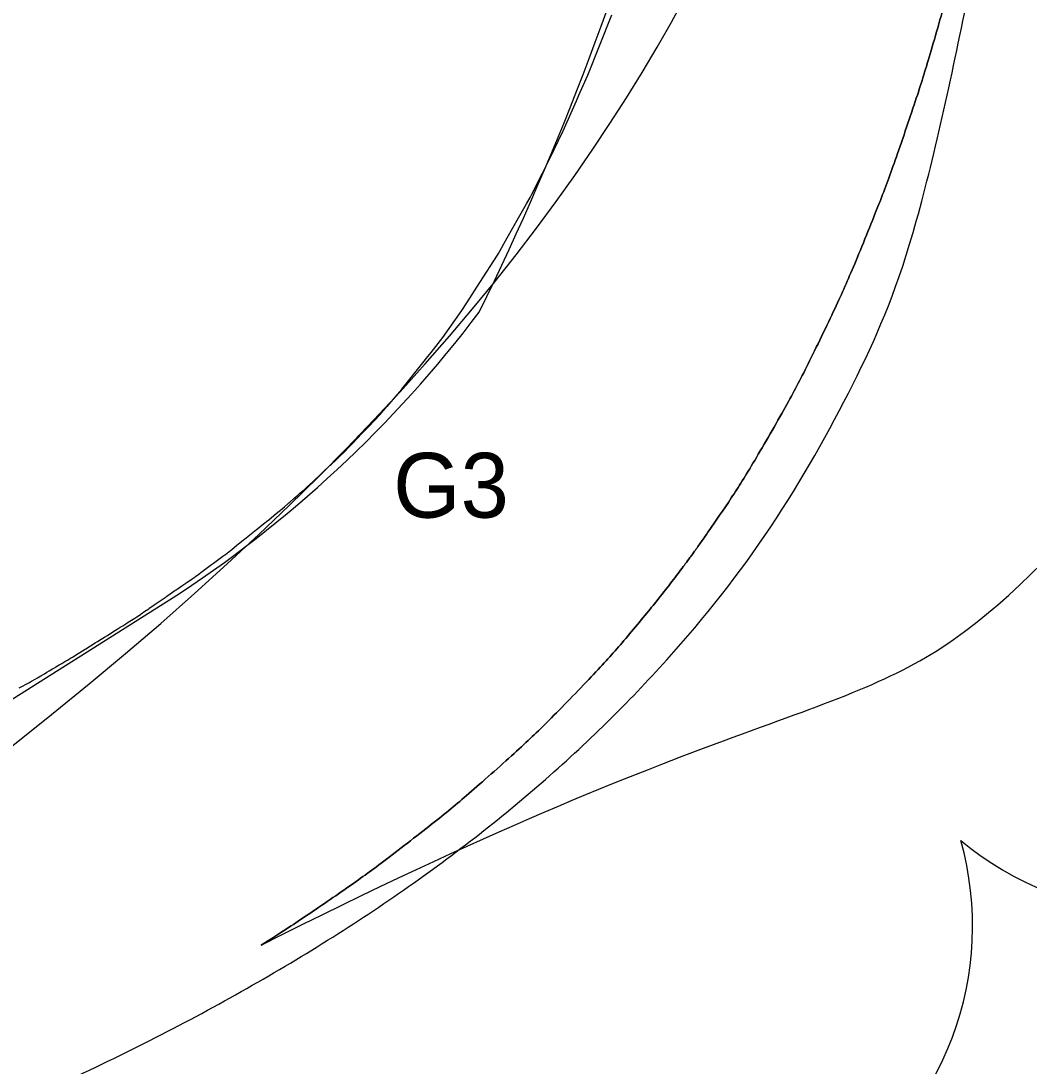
# Model space of a CAD drawing. Extents: x 0 to 512122, y 0 to 6212554.
# Drawn here: x 511655.18 to 511674.62, y 6211397.6 to 6211417.76 of the extents above; entities that cross this region are included whole.
import ezdxf

# ---------------------------------------------------------------- set-up
doc = ezdxf.new("R2010")
doc.units = 0
for name, color, linetype in [('_G3S_Slået græsser', 7, 'Continuous'), ('_Paths', 7, 'Continuous'), ('_S1_rabarber', 7, 'Continuous'), ('Clouds', 7, 'Continuous'), ('TV_U_AFM_Symbl_Gul', 7, 'Continuous'), ('TV_U_LYS_Nyx330-Trafiksti-x2', 7, 'Continuous')]:
    doc.layers.add(name, color=color, linetype=linetype)

msp = doc.modelspace()

# ---------------------------------------------------------------- linework, layer by layer
at = {"layer": '_G3S_Slået græsser'}
msp.add_lwpolyline([(511640.462, 6211394.164), (511651.9, 6211402.721), (511658.046, 6211406.592)], dxfattribs=at)
for centre, radius, start, end in [((511613.419, 6211436.972), 56.363, 333.8642, 344.7053), ((511645.363, 6211426.225), 23.373, 302.8622, 322.9556)]:
    msp.add_arc(centre, radius, start, end, dxfattribs=at)
at = {"layer": '_Paths'}
for points, degree in [([(511640.462, 6211394.164), (511666.005, 6211408.809), (511672.517, 6211429.483), (511676.559, 6211451.282), (511690.481, 6211465.664), (511705.077, 6211478.474), (511709.825, 6211494.014), (511640.462, 6211394.164), (511709.825, 6211494.014)], 3), ([(511651.32, 6211395.399), (511670.02, 6211402.099), (511675.836, 6211429.41), (511675.931, 6211450.773), (511691.497, 6211463.947), (511708.899, 6211474.665), (511711.288, 6211488), (511712.286, 6211493.573)], 2)]:
    msp.add_open_spline(points, degree=degree, dxfattribs=at)
at = {"layer": '_S1_rabarber'}
for points in [[(511659.815, 6211399.937), (511668.561, 6211404.361), (511673.198, 6211404.114), (511679.922, 6211414.023), (511688.007, 6211417.394), (511690.187, 6211425.291), (511687.866, 6211432.031), (511684.336, 6211437.489), (511684.603, 6211441.593), (511684.719, 6211443.38)], [(511659.815, 6211399.937), (511668.561, 6211404.361), (511673.198, 6211404.114), (511679.922, 6211414.023), (511688.007, 6211417.394), (511690.187, 6211425.291), (511687.866, 6211432.031), (511684.336, 6211437.489), (511684.603, 6211441.593), (511684.719, 6211443.38)], [(511659.815, 6211399.937), (511660.213, 6211400.189), (511660.606, 6211400.447), (511661.573, 6211401.109), (511662.14, 6211401.52), (511663.246, 6211402.378), (511663.784, 6211402.823), (511664.828, 6211403.751), (511665.333, 6211404.234), (511666.306, 6211405.238), (511666.774, 6211405.761), (511667.445, 6211406.576), (511667.663, 6211406.853), (511667.929, 6211407.206), (511667.982, 6211407.277), (511668.087, 6211407.42), (511668.139, 6211407.491), (511668.294, 6211407.707), (511668.396, 6211407.852), (511668.897, 6211408.58), (511669.273, 6211409.18), (511669.979, 6211410.406), (511670.309, 6211411.034), (511670.927, 6211412.312), (511671.214, 6211412.964), (511671.752, 6211414.286), (511672.001, 6211414.958), (511672.465, 6211416.317), (511672.68, 6211417.005), (511673.079, 6211418.394), (511673.262, 6211419.095), (511673.602, 6211420.507), (511673.759, 6211421.218), (511674.047, 6211422.648), (511674.179, 6211423.366), (511674.415, 6211424.772), (511674.521, 6211425.459), (511674.618, 6211426.146)], [(511674.618, 6211426.146), (511674.521, 6211425.459), (511674.415, 6211424.772), (511674.179, 6211423.366), (511674.047, 6211422.648), (511673.759, 6211421.218), (511673.602, 6211420.507), (511673.262, 6211419.095), (511673.079, 6211418.394), (511672.68, 6211417.005), (511672.465, 6211416.317), (511672.001, 6211414.958), (511671.752, 6211414.286), (511671.214, 6211412.964), (511670.927, 6211412.312), (511670.309, 6211411.034), (511669.979, 6211410.406), (511669.273, 6211409.18), (511668.897, 6211408.58), (511668.396, 6211407.852), (511668.294, 6211407.707), (511668.139, 6211407.491), (511668.087, 6211407.42), (511667.982, 6211407.277), (511667.929, 6211407.206), (511667.663, 6211406.853), (511667.445, 6211406.576), (511666.774, 6211405.761), (511666.306, 6211405.238), (511665.333, 6211404.234), (511664.828, 6211403.751), (511663.784, 6211402.823), (511663.246, 6211402.378), (511662.14, 6211401.52), (511661.573, 6211401.109), (511660.606, 6211400.447), (511660.213, 6211400.189), (511659.815, 6211399.937)]]:
    msp.add_open_spline(points, degree=3, dxfattribs=at)
at = {"layer": 'Clouds'}
for centre, radius, start, end in [((511656.443, 6211415.056), 6.101, 70.4825, 215.4825), ((511677.213, 6211406.637), 6.1, 230.1332, 15.1332), ((511667.429, 6211400.306), 6.1, 230.678, 15.678)]:
    msp.add_arc(centre, radius, start, end, dxfattribs=at)
at = {"layer": 'TV_U_LYS_Nyx330-Trafiksti-x2'}
for points in [[(511664.928, 6211414.23), (511664.997, 6211414.351), (511665.029, 6211414.415), (511665.236, 6211414.821), (511665.387, 6211415.118), (511665.54, 6211415.437), (511665.637, 6211415.64), (511665.894, 6211416.22), (511665.94, 6211416.324), (511665.965, 6211416.382), (511666.112, 6211416.714), (511666.571, 6211417.876)], [(511655.149, 6211404.897), (511655.225, 6211404.938), (511655.273, 6211404.964), (511655.334, 6211404.997), (511655.356, 6211405.009), (511655.368, 6211405.016), (511655.385, 6211405.025), (511655.457, 6211405.067), (511655.501, 6211405.093), (511655.567, 6211405.132), (511655.634, 6211405.171), (511655.682, 6211405.199), (511655.728, 6211405.226), (511655.793, 6211405.264), (511655.84, 6211405.292), (511655.858, 6211405.302), (511655.922, 6211405.34), (511655.973, 6211405.37), (511656.029, 6211405.403), (511656.078, 6211405.431), (511656.139, 6211405.467), (511656.173, 6211405.487), (511656.197, 6211405.501), (511656.246, 6211405.532), (511656.256, 6211405.538), (511656.318, 6211405.577), (511656.42, 6211405.641), (511656.425, 6211405.644), (511656.434, 6211405.65), (511656.614, 6211405.763), (511656.657, 6211405.789), (511656.728, 6211405.834), (511656.796, 6211405.877), (511656.848, 6211405.91), (511656.894, 6211405.938), (511656.948, 6211405.972), (511656.973, 6211405.988), (511657.037, 6211406.028), (511657.097, 6211406.066), (511657.144, 6211406.095), (511657.206, 6211406.134), (511657.252, 6211406.163), (511657.38, 6211406.243), (511657.394, 6211406.252), (511657.401, 6211406.257), (511657.414, 6211406.266), (511657.486, 6211406.315), (511657.503, 6211406.327), (511657.572, 6211406.374), (511657.645, 6211406.424), (511657.657, 6211406.433), (511657.724, 6211406.479), (511657.745, 6211406.493), (511657.75, 6211406.497), (511657.849, 6211406.565), (511657.885, 6211406.589), (511657.886, 6211406.59), (511657.904, 6211406.602), (511657.981, 6211406.655), (511657.997, 6211406.667), (511658.059, 6211406.709), (511658.15, 6211406.772), (511658.164, 6211406.781), (511658.173, 6211406.787), (511658.195, 6211406.803), (511658.281, 6211406.862), (511658.359, 6211406.915), (511658.369, 6211406.922), (511658.38, 6211406.93), (511658.484, 6211407.002), (511658.542, 6211407.041), (511658.552, 6211407.048), (511658.553, 6211407.049), (511658.584, 6211407.071), (511658.652, 6211407.122), (511658.675, 6211407.139), (511658.859, 6211407.274), (511658.892, 6211407.299), (511659.076, 6211407.435), (511659.096, 6211407.449), (511659.113, 6211407.462), (511659.123, 6211407.47), (511659.222, 6211407.549), (511659.245, 6211407.568), (511659.299, 6211407.611), (511659.351, 6211407.653), (511659.373, 6211407.67), (511659.442, 6211407.726), (511659.524, 6211407.791), (511659.558, 6211407.818), (511659.594, 6211407.847), (511659.662, 6211407.902), (511659.723, 6211407.951), (511659.747, 6211407.97), (511659.827, 6211408.034), (511659.887, 6211408.082), (511659.916, 6211408.105), (511659.959, 6211408.14), (511660.01, 6211408.18), (511660.058, 6211408.219), (511660.065, 6211408.225), (511660.17, 6211408.309), (511660.173, 6211408.311), (511660.177, 6211408.314), (511660.187, 6211408.322), (511660.262, 6211408.388), (511660.326, 6211408.444), (511660.343, 6211408.458), (511660.35, 6211408.465), (511660.365, 6211408.477), (511660.444, 6211408.546), (511660.52, 6211408.614), (511660.562, 6211408.65), (511660.622, 6211408.703), (511660.64, 6211408.718), (511660.697, 6211408.768), (511660.708, 6211408.778), (511660.741, 6211408.809), (511660.833, 6211408.896), (511660.847, 6211408.91), (511660.943, 6211409.001), (511660.978, 6211409.034), (511661.054, 6211409.105), (511661.061, 6211409.112), (511661.066, 6211409.116), (511661.143, 6211409.189), (511661.169, 6211409.214), (511661.244, 6211409.284), (511661.322, 6211409.358), (511661.424, 6211409.455), (511661.458, 6211409.49), (511661.466, 6211409.499), (511661.48, 6211409.513), (511661.586, 6211409.625), (511661.649, 6211409.691), (511661.655, 6211409.698), (511661.664, 6211409.707), (511661.755, 6211409.802), (511661.793, 6211409.842), (511661.886, 6211409.939), (511662.101, 6211410.165), (511662.244, 6211410.328), (511662.259, 6211410.345), (511662.268, 6211410.356), (511662.274, 6211410.363), (511662.28, 6211410.37), (511662.526, 6211410.651), (511662.528, 6211410.654), (511662.957, 6211411.199), (511663.004, 6211411.258), (511663.089, 6211411.365), (511663.316, 6211411.654), (511663.683, 6211412.172), (511663.779, 6211412.321), (511664.03, 6211412.712), (511664.369, 6211413.239), (511664.39, 6211413.276), (511664.559, 6211413.576), (511664.776, 6211413.96), (511664.928, 6211414.23)]]:
    msp.add_lwpolyline(points, dxfattribs=at)

# ---------------------------------------------------------------- texts
at = {"layer": 'TV_U_AFM_Symbl_Gul'}
msp.add_text('G3', height=1.25, dxfattribs=at).set_placement((511662.359, 6211408.179))

doc.saveas('drawing.dxf')
